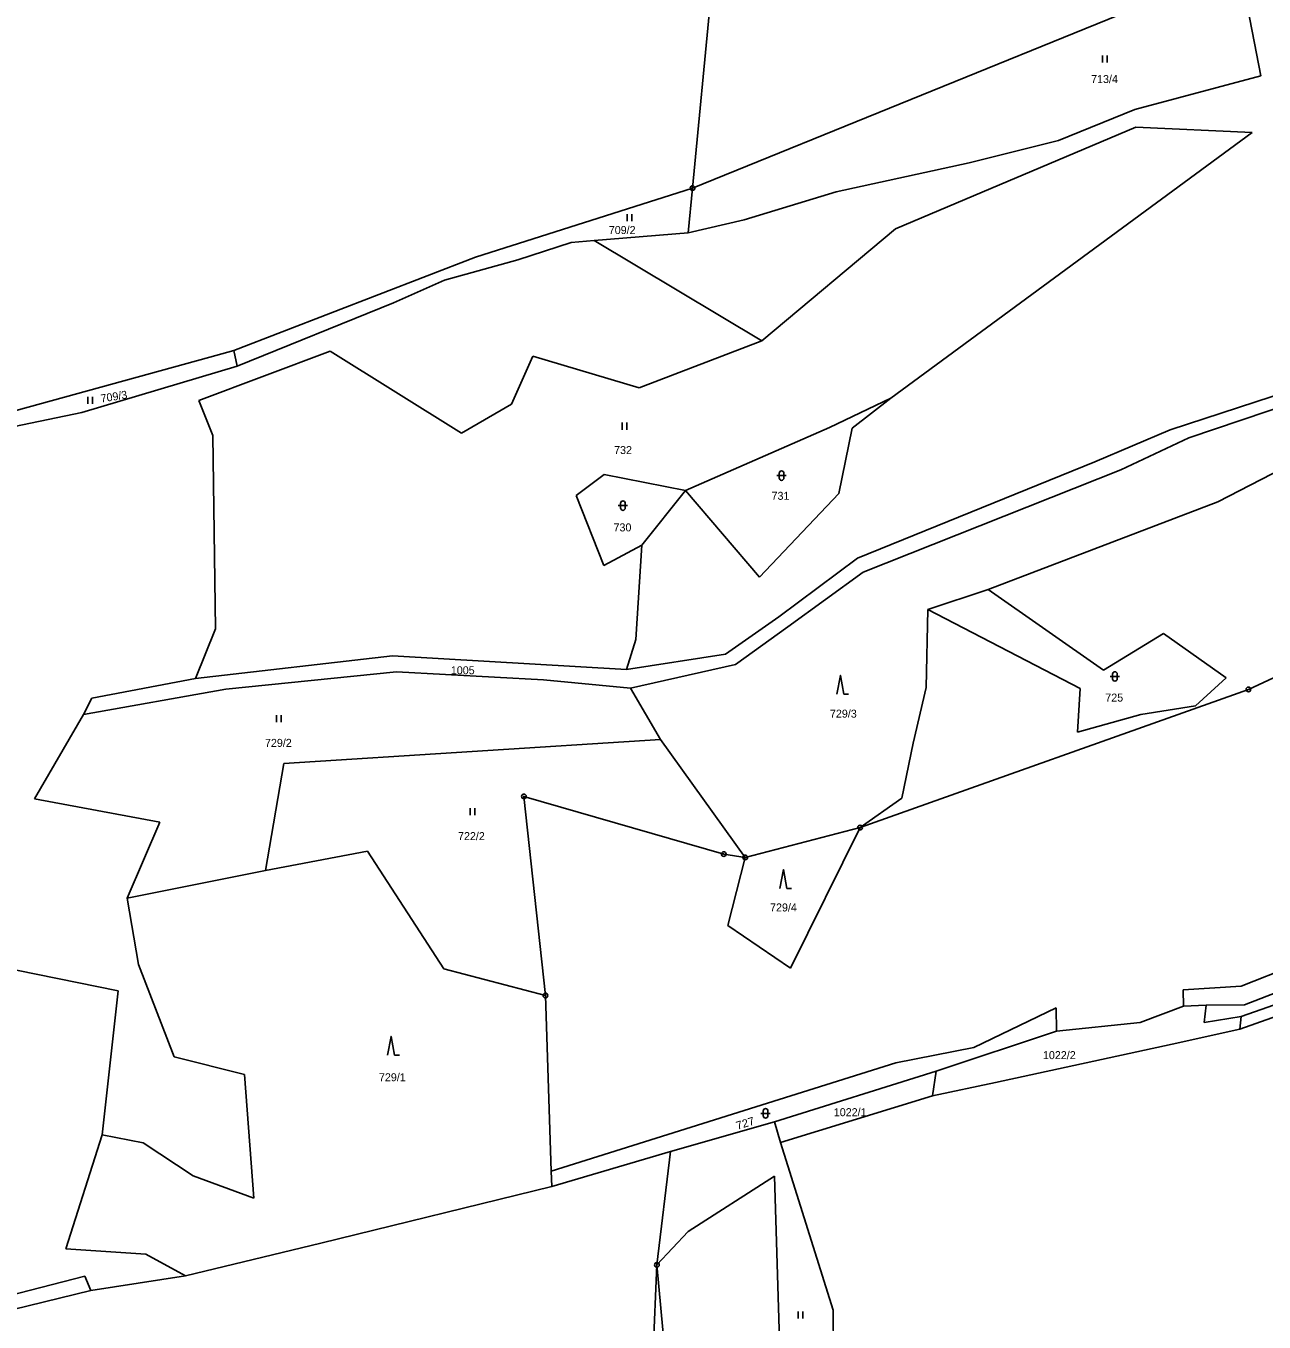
# Model space of a CAD drawing. Extents: x -754970 to -752637, y -970569 to -968179.
# Drawn here: x -754392.6 to -754129.7, y -969953.5 to -969678.2 of the extents above; entities that cross this region are included whole.
import ezdxf
from ezdxf.enums import TextEntityAlignment as Align

# ---------------------------------------------------------------- set-up
doc = ezdxf.new("R2010")
doc.units = 0
doc.header["$LTSCALE"] = 0.68
for name, color, linetype, lineweight in [('1', 7, 'Continuous', 25), ('3', 7, 'Continuous', 25), ('8', 7, 'Continuous', 25)]:
    doc.layers.add(name, color=color, linetype=linetype, lineweight=lineweight)
doc.layers.add('2', color=7, linetype='Continuous')

msp = doc.modelspace()

# ---------------------------------------------------------------- linework, layer by layer
at = {"layer": '1'}
for p, q in [((-754242.13, -969619.47), (-754251.03, -969712.66)), ((-754141.6, -969631.12), (-754130.34, -969688.78)), ((-754158.31, -969675.02), (-754251.03, -969712.66)), ((-754130.34, -969688.78), (-754157.13, -969695.93)), ((-754157.13, -969695.93), (-754173.33, -969702.55)), ((-754132.23, -969700.86), (-754208.91, -969757.31)), ((-754207.92, -969721.3), (-754156.89, -969699.71)), ((-754156.89, -969699.71), (-754132.23, -969700.86)), ((-754173.33, -969702.55), (-754192.26, -969707.29)), ((-754192.26, -969707.29), (-754220.52, -969713.44)), ((-754251.03, -969712.66), (-754297.11, -969727.3)), ((-754251.03, -969712.66), (-754251.96, -969722.19)), ((-754236.34, -969745.12), (-754207.92, -969721.3)), ((-754276.79, -969724.24), (-754288.09, -969727.92)), ((-754271.89, -969723.8), (-754276.79, -969724.24)), ((-754271.89, -969723.8), (-754236.34, -969745.12)), ((-754297.11, -969727.3), (-754348.43, -969747.18)), ((-754288.09, -969727.92), (-754303.68, -969732.21)), ((-754303.68, -969732.21), (-754314.53, -969737.03)), ((-754347.7, -969750.5), (-754314.53, -969737.03)), ((-754236.34, -969745.12), (-754262.34, -969755.07)), ((-754327.94, -969747.27), (-754355.87, -969757.78)), ((-754348.43, -969747.18), (-754353.51, -969748.57)), ((-754347.7, -969750.5), (-754348.43, -969747.18)), ((-754327.94, -969747.27), (-754300.09, -969764.7)), ((-754353.51, -969748.57), (-754394.94, -969759.98)), ((-754380.69, -969760.33), (-754347.7, -969750.5)), ((-754284.94, -969748.33), (-754289.49, -969758.57)), ((-754262.34, -969755.07), (-754284.94, -969748.33)), ((-754124.26, -969755.69), (-754149.61, -969764)), ((-754355.87, -969757.78), (-754352.89, -969765.23)), ((-754289.49, -969758.57), (-754300.09, -969764.7)), ((-754208.91, -969757.31), (-754221.96, -969763.52)), ((-754217.17, -969763.68), (-754208.91, -969757.31)), ((-754145.62, -969765.72), (-754123.29, -969758.17)), ((-754139.48, -969779.31), (-754095.67, -969756.55)), ((-754399.09, -969764.13), (-754380.69, -969760.33)), ((-754221.96, -969763.52), (-754252.55, -969776.89)), ((-754220, -969777.52), (-754217.17, -969763.68)), ((-754149.61, -969764), (-754165.59, -969770.79)), ((-754352.89, -969765.23), (-754352.33, -969806.27)), ((-754160.09, -969772.51), (-754145.62, -969765.72)), ((-754216.01, -969791.29), (-754165.59, -969770.79)), ((-754160.09, -969772.51), (-754214.83, -969794.24)), ((-754275.74, -969777.95), (-754269.81, -969773.51)), ((-754269.81, -969773.51), (-754252.55, -969776.89)), ((-754132.99, -969819.13), (-754036.61, -969774.4)), ((-754269.85, -969792.81), (-754275.74, -969777.95)), ((-754252.55, -969776.89), (-754261.83, -969788.49)), ((-754252.55, -969776.89), (-754236.82, -969795.29)), ((-754236.82, -969795.29), (-754220, -969777.52)), ((-754188.25, -969797.88), (-754139.48, -969779.31)), ((-754261.83, -969788.49), (-754269.85, -969792.81)), ((-754263.07, -969808.57), (-754261.83, -969788.49)), ((-754232.69, -969803.71), (-754216.01, -969791.29)), ((-754214.83, -969794.24), (-754230.79, -969805.84)), ((-754201.09, -969802.19), (-754188.25, -969797.88)), ((-754188.25, -969797.88), (-754163.76, -969815.04)), ((-754201.41, -969818.71), (-754201.09, -969802.19)), ((-754201.09, -969802.19), (-754168.72, -969818.92)), ((-754232.69, -969803.71), (-754244.05, -969811.64)), ((-754230.79, -969805.84), (-754241.92, -969813.84)), ((-754352.33, -969806.27), (-754356.55, -969816.85)), ((-754265.03, -969814.94), (-754263.07, -969808.57)), ((-754151.03, -969807.27), (-754163.76, -969815.04)), ((-754137.75, -969816.66), (-754151.03, -969807.27)), ((-754356.55, -969816.85), (-754314.77, -969812)), ((-754314.77, -969812), (-754265.03, -969814.94)), ((-754265.03, -969814.94), (-754244.05, -969811.64)), ((-754241.92, -969813.84), (-754264.23, -969818.85)), ((-754356.55, -969816.85), (-754378.61, -969821)), ((-754350.12, -969819.07), (-754313.87, -969815.39)), ((-754313.87, -969815.39), (-754282.68, -969817.12)), ((-754144.23, -969822.59), (-754137.75, -969816.66)), ((-754380.34, -969824.47), (-754350.12, -969819.07)), ((-754264.23, -969818.85), (-754282.68, -969817.12)), ((-754257.86, -969829.77), (-754264.23, -969818.85)), ((-754215.44, -969848.48), (-754132.99, -969819.13)), ((-754204.22, -969830.58), (-754201.41, -969818.71)), ((-754168.72, -969818.92), (-754169.26, -969828.21)), ((-754378.61, -969821), (-754380.34, -969824.47)), ((-754155.88, -969824.43), (-754144.23, -969822.59)), ((-754380.34, -969824.47), (-754390.78, -969842.39)), ((-754169.26, -969828.21), (-754155.88, -969824.43)), ((-754257.86, -969829.77), (-754337.81, -969834.84)), ((-754239.85, -969854.81), (-754257.86, -969829.77)), ((-754206.59, -969842.24), (-754204.22, -969830.58)), ((-754341.68, -969857.6), (-754337.81, -969834.84)), ((-754286.83, -969841.86), (-754244.42, -969854.1)), ((-754282.28, -969884.15), (-754286.83, -969841.86)), ((-754390.78, -969842.39), (-754364.16, -969847.3)), ((-754215.44, -969848.48), (-754206.59, -969842.24)), ((-754371.07, -969863.49), (-754364.16, -969847.3)), ((-754239.85, -969854.81), (-754215.44, -969848.48)), ((-754230.26, -969878.35), (-754215.44, -969848.48)), ((-754320.03, -969853.51), (-754341.68, -969857.6)), ((-754303.82, -969878.48), (-754320.03, -969853.51)), ((-754244.42, -969854.1), (-754239.85, -969854.81)), ((-754239.85, -969854.81), (-754243.54, -969869.29)), ((-754341.68, -969857.6), (-754371.07, -969863.49)), ((-754371.07, -969863.49), (-754368.67, -969877.58)), ((-754467.01, -969863.95), (-754372.96, -969883.19)), ((-754243.54, -969869.29), (-754230.26, -969878.35)), ((-754100.7, -969868.84), (-754134.54, -969882.17)), ((-754133.86, -969886.14), (-754100.35, -969873.08)), ((-754368.67, -969877.58), (-754361.12, -969897.21)), ((-754134.54, -969888.6), (-754098.98, -969876.02)), ((-754282.28, -969884.15), (-754303.82, -969878.48)), ((-754101.99, -969879.78), (-754134.81, -969891.27)), ((-754134.54, -969882.17), (-754146.85, -969882.93)), ((-754146.85, -969882.93), (-754146.78, -969886.41)), ((-754376.38, -969913.71), (-754372.96, -969883.19)), ((-754281.02, -969921.49), (-754282.28, -969884.15)), ((-754191.3, -969895.19), (-754173.79, -969886.78)), ((-754173.79, -969886.78), (-754173.72, -969891.73)), ((-754146.78, -969886.41), (-754156, -969889.85)), ((-754141.99, -969886.21), (-754146.78, -969886.41)), ((-754142.4, -969889.9), (-754141.99, -969886.21)), ((-754134.54, -969888.6), (-754142.4, -969889.9)), ((-754141.99, -969886.21), (-754133.86, -969886.14)), ((-754134.81, -969891.27), (-754134.54, -969888.6)), ((-754156, -969889.85), (-754173.72, -969891.73)), ((-754149.16, -969894.5), (-754134.81, -969891.27)), ((-754173.72, -969891.73), (-754199.3, -969900.21)), ((-754207.86, -969898.48), (-754191.3, -969895.19)), ((-754186.69, -969902.64), (-754149.16, -969894.5)), ((-754361.12, -969897.21), (-754346.18, -969900.94)), ((-754281.02, -969921.49), (-754207.86, -969898.48)), ((-754346.18, -969900.94), (-754344.15, -969927.19)), ((-754199.3, -969900.21), (-754233.6, -969910.97)), ((-754199.3, -969900.21), (-754200.09, -969905.44)), ((-754200.09, -969905.44), (-754186.69, -969902.64)), ((-754232.35, -969915.36), (-754200.09, -969905.44)), ((-754233.6, -969910.97), (-754255.74, -969917.25)), ((-754233.6, -969910.97), (-754232.35, -969915.36)), ((-754376.38, -969913.71), (-754384.1, -969937.93)), ((-754367.66, -969915.43), (-754376.38, -969913.71)), ((-754357.07, -969922.44), (-754367.66, -969915.43)), ((-754221.2, -969951.01), (-754232.35, -969915.36)), ((-754280.94, -969924.71), (-754255.74, -969917.25)), ((-754258.61, -969941.38), (-754255.74, -969917.25)), ((-754280.94, -969924.71), (-754281.02, -969921.49)), ((-754344.15, -969927.19), (-754357.07, -969922.44)), ((-754251.97, -969934.29), (-754233.6, -969922.51)), ((-754233.6, -969922.51), (-754232.03, -969975.11)), ((-754329.95, -969936.77), (-754280.94, -969924.71)), ((-754258.61, -969941.38), (-754251.97, -969934.29)), ((-754384.1, -969937.93), (-754367.13, -969939.1)), ((-754358.72, -969943.69), (-754329.95, -969936.77)), ((-754367.13, -969939.1), (-754358.72, -969943.69)), ((-754358.72, -969943.69), (-754378.81, -969946.81)), ((-754261.38, -970006.14), (-754258.61, -969941.38)), ((-754258.61, -969941.38), (-754253.64, -969995.86)), ((-754402.32, -969949.46), (-754380.05, -969943.77)), ((-754380.05, -969943.77), (-754378.81, -969946.81)), ((-754378.81, -969946.81), (-754402.4, -969952.57)), ((-754221.04, -969967.97), (-754221.2, -969951.01))]:
    msp.add_line(p, q, dxfattribs=at)
msp.add_lwpolyline([(-754220.52, -969713.44), (-754240.07, -969719.41), (-754251.96, -969722.19), (-754271.89, -969723.8)], dxfattribs=at)
at = {"layer": '3'}
for p, q in [((-754163.971, -969685.98), (-754163.971, -969684.48)), ((-754162.97, -969685.98), (-754162.97, -969684.48)), ((-754264.891, -969719.69), (-754264.891, -969718.19)), ((-754263.89, -969719.69), (-754263.89, -969718.19)), ((-754379.451, -969758.51), (-754379.451, -969757.01)), ((-754378.45, -969758.51), (-754378.45, -969757.01)), ((-754266.001, -969763.97), (-754266.001, -969762.47)), ((-754265, -969763.97), (-754265, -969762.47)), ((-754233.141, -969773.731), (-754231.139, -969773.731)), ((-754232.641, -969773.231), (-754232.641, -969774.232)), ((-754231.639, -969774.232), (-754231.639, -969773.231)), ((-754266.811, -969780.101), (-754264.809, -969780.101)), ((-754266.311, -969779.601), (-754266.311, -969780.602)), ((-754265.309, -969780.602), (-754265.309, -969779.601)), ((-754162.351, -969816.381), (-754160.349, -969816.381)), ((-754161.851, -969815.881), (-754161.851, -969816.882)), ((-754160.849, -969816.882), (-754160.849, -969815.881)), ((-754218.89, -969820.17), (-754217.894, -969820.17)), ((-754339.391, -969826.1), (-754339.391, -969824.6)), ((-754338.39, -969826.1), (-754338.39, -969824.6)), ((-754298.251, -969845.87), (-754298.251, -969844.37)), ((-754297.25, -969845.87), (-754297.25, -969844.37)), ((-754230.98, -969861.42), (-754229.984, -969861.42)), ((-754314.28, -969896.85), (-754313.284, -969896.85)), ((-754236.521, -969909.181), (-754234.519, -969909.181)), ((-754236.021, -969908.681), (-754236.021, -969909.682)), ((-754235.019, -969909.682), (-754235.019, -969908.681)), ((-754228.581, -969952.75), (-754228.581, -969951.25)), ((-754227.58, -969952.75), (-754227.58, -969951.25))]:
    msp.add_line(p, q, dxfattribs=at)
for points in [[(-754218.89, -969820.17), (-754219.64, -969816.17), (-754220.39, -969820.17)], [(-754230.98, -969861.42), (-754231.73, -969857.42), (-754232.48, -969861.42)], [(-754314.28, -969896.85), (-754315.03, -969892.85), (-754315.78, -969896.85)]]:
    msp.add_lwpolyline(points, dxfattribs=at)
for centre, start, end in [((-754232.14, -969773.2309), 0, 180), ((-754232.14, -969774.2309), 180, 359.98789), ((-754265.81, -969779.6009), 0, 180), ((-754265.81, -969780.6009), 180, 359.98789), ((-754161.35, -969815.8809), 0, 180), ((-754161.35, -969816.8809), 180, 359.98789), ((-754235.52, -969908.6809), 0, 180), ((-754235.52, -969909.6809), 180, 359.98789)]:
    msp.add_arc(centre, 0.5, start, end, dxfattribs=at)
at = {"layer": '8'}
for centre, radius in [((-754251.03, -969712.6599), 0.5), ((-754251.03, -969712.6599), 0.0303), ((-754132.99, -969819.1299), 0.5), ((-754132.99, -969819.1299), 0.0303), ((-754286.83, -969841.8599), 0.5), ((-754286.83, -969841.8599), 0.0303), ((-754215.44, -969848.4799), 0.5), ((-754215.44, -969848.4799), 0.0303), ((-754244.42, -969854.0999), 0.5), ((-754244.42, -969854.0999), 0.0303), ((-754239.85, -969854.8099), 0.5), ((-754239.85, -969854.8099), 0.0303), ((-754282.28, -969884.1499), 0.5), ((-754282.28, -969884.1499), 0.0303), ((-754258.61, -969941.3799), 0.5), ((-754258.61, -969941.3799), 0.0303)]:
    msp.add_circle(centre, radius, dxfattribs=at)

# ---------------------------------------------------------------- texts
at = {"layer": '2'}
for s, p in [('713/4', (-754163.56, -969690.345)), ('709/2', (-754265.97, -969722.415)), ('732', (-754265.789, -969769.145)), ('731', (-754232.359, -969778.865)), ('730', (-754265.909, -969785.575)), ('1005', (-754299.82, -969815.925)), ('725', (-754161.499, -969821.725)), ('729/3', (-754219.01, -969825.135)), ('729/2', (-754338.97, -969831.345)), ('722/2', (-754297.98, -969851.145)), ('729/4', (-754231.73, -969866.295)), ('1022/2', (-754173.15, -969897.665)), ('729/1', (-754314.77, -969902.365)), ('1022/1', (-754217.56, -969909.785))]:
    msp.add_text(s, height=1.7, dxfattribs=at).set_placement(p, align=Align.CENTER)
msp.add_text('709/3', height=1.7, rotation=9, dxfattribs=at).set_placement((-754373.755, -969757.7686), align=Align.CENTER)
at = {"layer": '2', "width": 1.05}
msp.add_text('727', height=1.7, rotation=17, dxfattribs=at).set_placement((-754239.599, -969912.0974), align=Align.CENTER)

doc.saveas('drawing.dxf')
